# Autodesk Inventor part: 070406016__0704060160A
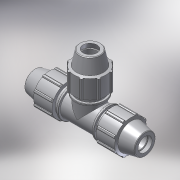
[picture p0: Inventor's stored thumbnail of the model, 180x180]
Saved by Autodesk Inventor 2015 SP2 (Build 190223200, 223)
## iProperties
Created: 2017-02
Part Number: 070406016__0704060160A
Material: PVC-Piping
Description: PLASSON TEE 16-16-16
Document SubType Name: Modeling
Designer: KIM
Mass: 92.6774 g
Surface Area: 199.44 cm^2
Volume: 66.1981 cm^3
Density: 1.4 g/cm^3
Appearance: Smooth - White
Author: KIM
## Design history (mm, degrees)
derived "07040.ipt"
feature "Solid1::07040.ipt"
tag "TaggingFeature1"
body "Solid1"
other parameters: "d2" = 16, "d4" = 5.25, "d5" = 15.75, "d7" = 39, "d11" = 2.1, "d13" = 120 deg, "d14" = 24, "d15" = 12 deg, "d16" = 33.93, "d18" = 0.8, "d19" = 35 deg, "d20" = 17.5 deg, "d21" = 36.27, "d23" = 0, "d25" = 360 deg, "d27" = 0.78, "d33" = 0.32, "d42" = 22.05, "d43" = 1.17, "d46" = 0.48, "d67" = 29.25, "d76" = 16, "d77" = 39, "d78" = 12 deg, "d79" = 63, "d80" = 120 deg, "d81" = 24, "d82" = 5.25, "d85" = 29.25, "d86" = 33.93, "d87" = 2.1, "d88" = 2.1, "d89" = 15.75, "d90" = 22.05, "d96" = 6.3, "d98" = 36.27, "d99" = 35 deg, "d100" = 17.5 deg, "d102" = 0, "d103" = 0.78, "d107" = 360 deg, "d109" = 0.48, "d112" = 0.8, "d118" = 360 deg, "d121" = 0, "d128" = 126, "d131" = 14.4, "d132" = 14.4, "d134" = 1, "d135" = 6.3, "d152" = 0, "d154" = 0, "d156" = 0, "d158" = 0, "d_" = 16, "E_" = 39, "A_" = 63, "H_" = 126
